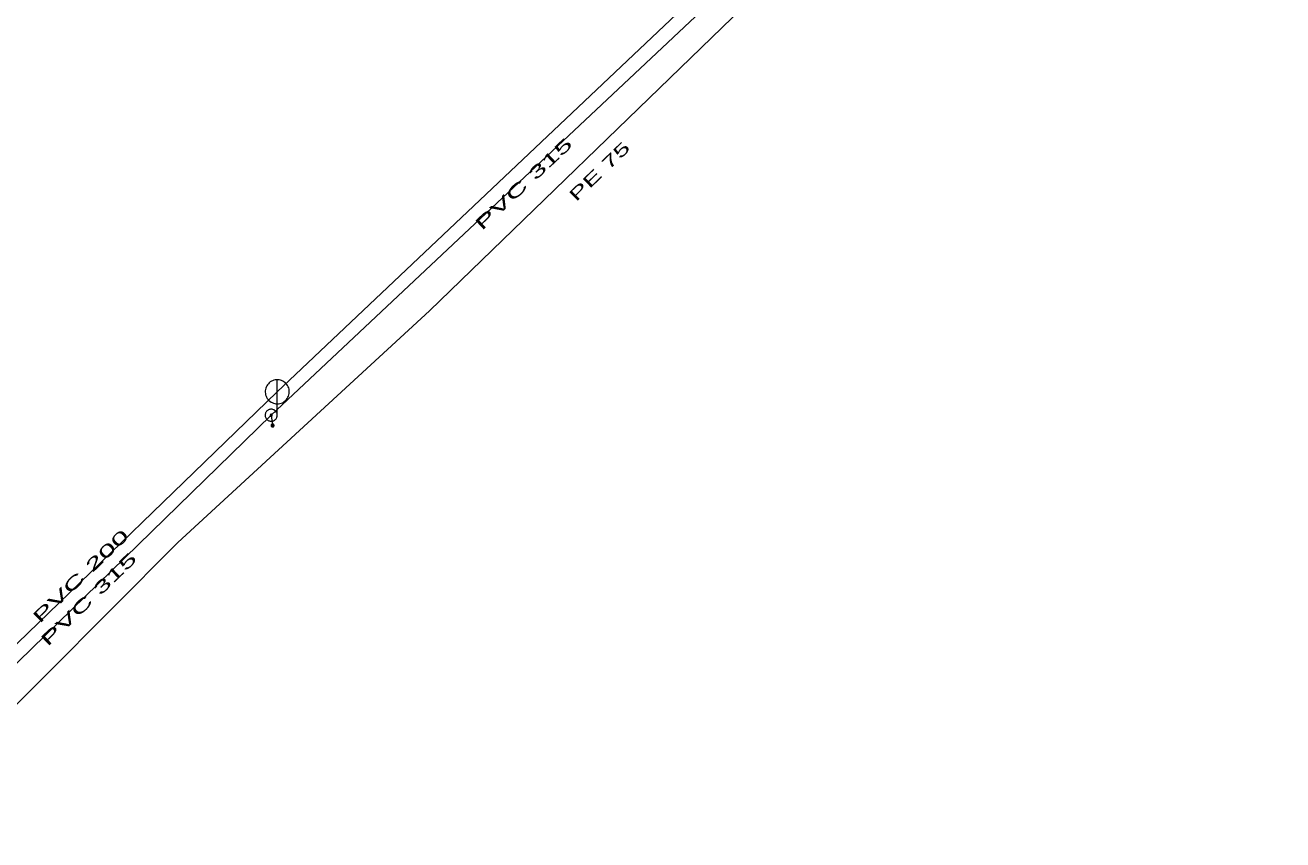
# Model space of a CAD drawing. Extents: x -807203 to -805207, y -993656 to -992505.
# Drawn here: x -806626.5 to -806522, y -992921.3 to -992853.6 of the extents above; entities that cross this region are included whole.
import ezdxf

# ---------------------------------------------------------------- set-up
doc = ezdxf.new("R2010")
doc.units = 0
doc.header["$LTSCALE"] = 0.4
for name, color, linetype, lineweight in [('1', 7, 'Continuous', 13), ('14', 7, 'Continuous', 25), ('17', 7, 'Continuous', 25), ('22', 7, 'Continuous', 13), ('47', 7, 'Continuous', 13), ('9', 7, 'Continuous', 13)]:
    doc.layers.add(name, color=color, linetype=linetype, lineweight=lineweight)

msp = doc.modelspace()

# ---------------------------------------------------------------- linework, layer by layer
at = {"layer": '14'}
for p, q in [((-806569.21, -992849.649), (-806605.559, -992884.039)), ((-806605.559, -992884.039), (-806641.469, -992918.76))]:
    msp.add_line(p, q, dxfattribs=at)
at = {"layer": '14', "lineweight": 13}
msp.add_line((-806606.07, -992885.989), (-806605.949, -992886.839), dxfattribs=at)
at = {"layer": '14'}
msp.add_lwpolyline([(-806661.839, -993034.149), (-806676.42, -993009.03), (-806687.16, -992991.6), (-806684.379, -992974.399), (-806682.55, -992964.73), (-806665.699, -992948.5), (-806650.699, -992933.289), (-806630.39, -992913.17), (-806613.82, -992896.559), (-806592.899, -992877.32), (-806567.719, -992852.94), (-806551.12, -992836.629), (-806563.8, -992821.69), (-806562.329, -992819.699), (-806552.96, -992810.51), (-806551.289, -992809.149), (-806548.55, -992808.109), (-806545.73, -992809.739), (-806532.96, -992817.94), (-806527.999, -992817.239)], dxfattribs=at)
at = {"layer": '17'}
for points in [[(-806606.07, -992885.989), (-806568.51, -992850.699), (-806566.809, -992849.02), (-806561.074, -992843.828), (-806559.778, -992843.379), (-806556.037, -992839.954), (-806552.131, -992836.175), (-806521.969, -992807.139)], [(-806698.289, -992977.488), (-806696.94, -992976.539), (-806688.559, -992968), (-806676.219, -992954.809), (-806667.649, -992946.309), (-806638.16, -992917.219), (-806606.07, -992885.989)]]:
    msp.add_lwpolyline(points, dxfattribs=at)
at = {"layer": '22'}
msp.add_line((-806605.559, -992886.039), (-806605.558, -992883.039), dxfattribs=at)
msp.add_lwpolyline([(-806604.559, -992884.039), (-806604.564, -992883.93), (-806604.582, -992883.822), (-806604.612, -992883.716), (-806604.652, -992883.615), (-806604.704, -992883.518), (-806604.766, -992883.428), (-806604.838, -992883.345), (-806604.918, -992883.271), (-806605.006, -992883.205), (-806605.1, -992883.15), (-806605.2, -992883.105), (-806605.305, -992883.072), (-806605.412, -992883.05), (-806605.521, -992883.04), (-806605.631, -992883.042), (-806605.739, -992883.056), (-806605.846, -992883.081), (-806605.949, -992883.118), (-806606.047, -992883.167), (-806606.139, -992883.225), (-806606.225, -992883.294), (-806606.302, -992883.371), (-806606.371, -992883.457), (-806606.43, -992883.549), (-806606.478, -992883.647), (-806606.515, -992883.75), (-806606.541, -992883.857), (-806606.555, -992883.965), (-806606.558, -992884.075), (-806606.548, -992884.184), (-806606.527, -992884.291), (-806606.493, -992884.395), (-806606.449, -992884.495), (-806606.394, -992884.59), (-806606.328, -992884.678), (-806606.254, -992884.758), (-806606.171, -992884.83), (-806606.081, -992884.892), (-806605.985, -992884.944), (-806605.883, -992884.985), (-806605.778, -992885.015), (-806605.67, -992885.033), (-806605.56, -992885.039), (-806605.451, -992885.033), (-806605.343, -992885.015), (-806605.238, -992884.986), (-806605.136, -992884.945), (-806605.039, -992884.893), (-806604.949, -992884.831), (-806604.866, -992884.76), (-806604.791, -992884.68), (-806604.726, -992884.592), (-806604.67, -992884.498), (-806604.626, -992884.398), (-806604.592, -992884.294), (-806604.57, -992884.186), (-806604.56, -992884.077)], close=True, dxfattribs=at)
at = {"layer": '47'}
for points in [[(-806605.705, -992885.646), (-806605.743, -992885.61), (-806605.784, -992885.578), (-806605.829, -992885.551), (-806605.875, -992885.528), (-806605.925, -992885.51), (-806605.976, -992885.498), (-806606.028, -992885.491), (-806606.08, -992885.489), (-806606.132, -992885.493), (-806606.184, -992885.502), (-806606.234, -992885.516), (-806606.283, -992885.537), (-806606.329, -992885.561), (-806606.372, -992885.591), (-806606.412, -992885.624), (-806606.448, -992885.662), (-806606.48, -992885.703), (-806606.508, -992885.748), (-806606.53, -992885.794), (-806606.548, -992885.844), (-806606.56, -992885.895), (-806606.568, -992885.948), (-806606.569, -992886), (-806606.566, -992886.052), (-806606.556, -992886.103), (-806606.542, -992886.153), (-806606.522, -992886.202), (-806606.497, -992886.248), (-806606.467, -992886.291), (-806606.434, -992886.331), (-806606.396, -992886.367), (-806606.355, -992886.399), (-806606.31, -992886.427), (-806606.264, -992886.449), (-806606.214, -992886.467), (-806606.163, -992886.48), (-806606.111, -992886.487), (-806606.059, -992886.489), (-806606.006, -992886.485), (-806605.955, -992886.475), (-806605.905, -992886.461), (-806605.857, -992886.442), (-806605.81, -992886.416), (-806605.767, -992886.386), (-806605.727, -992886.353), (-806605.691, -992886.315), (-806605.659, -992886.274), (-806605.631, -992886.23), (-806605.609, -992886.183), (-806605.591, -992886.133), (-806605.578, -992886.082), (-806605.571, -992886.031), (-806605.57, -992885.979), (-806605.574, -992885.926), (-806605.583, -992885.874), (-806605.597, -992885.824), (-806605.617, -992885.776), (-806605.642, -992885.729), (-806605.672, -992885.686)], [(-806606.01, -992885.932), (-806606.016, -992885.926), (-806606.023, -992885.921), (-806606.03, -992885.917), (-806606.037, -992885.913), (-806606.046, -992885.91), (-806606.054, -992885.908), (-806606.063, -992885.907), (-806606.071, -992885.906), (-806606.08, -992885.908), (-806606.088, -992885.909), (-806606.097, -992885.911), (-806606.105, -992885.915), (-806606.112, -992885.919), (-806606.119, -992885.923), (-806606.126, -992885.929), (-806606.132, -992885.935), (-806606.137, -992885.942), (-806606.141, -992885.949), (-806606.145, -992885.956), (-806606.148, -992885.965), (-806606.15, -992885.973), (-806606.151, -992885.982), (-806606.152, -992885.99), (-806606.151, -992885.999), (-806606.149, -992886.007), (-806606.147, -992886.016), (-806606.143, -992886.024), (-806606.139, -992886.031), (-806606.135, -992886.038), (-806606.129, -992886.045), (-806606.123, -992886.051), (-806606.116, -992886.056), (-806606.109, -992886.06), (-806606.102, -992886.064), (-806606.093, -992886.067), (-806606.085, -992886.069), (-806606.076, -992886.07), (-806606.068, -992886.071), (-806606.059, -992886.07), (-806606.051, -992886.068), (-806606.042, -992886.066), (-806606.034, -992886.062), (-806606.027, -992886.058), (-806606.02, -992886.054), (-806606.013, -992886.048), (-806606.007, -992886.042), (-806606.002, -992886.035), (-806605.998, -992886.028), (-806605.994, -992886.021), (-806605.991, -992886.012), (-806605.989, -992886.004), (-806605.988, -992885.995), (-806605.987, -992885.987), (-806605.989, -992885.978), (-806605.99, -992885.97), (-806605.992, -992885.961), (-806605.996, -992885.953), (-806606, -992885.946), (-806606.004, -992885.939)]]:
    msp.add_lwpolyline(points, close=True, dxfattribs=at)
at = {"layer": '9'}
for points in [[(-806606.075, -992886.839), (-806606.075, -992886.852), (-806606.073, -992886.865), (-806606.07, -992886.878), (-806606.065, -992886.89), (-806606.059, -992886.902), (-806606.052, -992886.913), (-806606.044, -992886.923), (-806606.034, -992886.933), (-806606.024, -992886.941), (-806606.013, -992886.948), (-806606.001, -992886.954), (-806605.989, -992886.959), (-806605.976, -992886.962), (-806605.963, -992886.964), (-806605.95, -992886.966), (-806605.937, -992886.965), (-806605.924, -992886.963), (-806605.911, -992886.96), (-806605.899, -992886.955), (-806605.887, -992886.949), (-806605.876, -992886.942), (-806605.866, -992886.934), (-806605.856, -992886.924), (-806605.848, -992886.914), (-806605.841, -992886.903), (-806605.835, -992886.891), (-806605.83, -992886.879), (-806605.827, -992886.866), (-806605.825, -992886.853), (-806605.823, -992886.84), (-806605.824, -992886.827), (-806605.826, -992886.814), (-806605.829, -992886.801), (-806605.834, -992886.789), (-806605.84, -992886.777), (-806605.847, -992886.766), (-806605.855, -992886.756), (-806605.865, -992886.746), (-806605.875, -992886.738), (-806605.886, -992886.731), (-806605.898, -992886.725), (-806605.91, -992886.72), (-806605.923, -992886.717), (-806605.936, -992886.715), (-806605.949, -992886.714), (-806605.962, -992886.714), (-806605.975, -992886.716), (-806605.988, -992886.719), (-806606, -992886.724), (-806606.012, -992886.73), (-806606.023, -992886.737), (-806606.033, -992886.745), (-806606.043, -992886.755), (-806606.051, -992886.765), (-806606.058, -992886.776), (-806606.064, -992886.788), (-806606.069, -992886.8), (-806606.072, -992886.813), (-806606.074, -992886.826)], [(-806606.055, -992886.839), (-806606.056, -992886.85), (-806606.054, -992886.861), (-806606.051, -992886.872), (-806606.047, -992886.882), (-806606.042, -992886.892), (-806606.036, -992886.901), (-806606.029, -992886.91), (-806606.021, -992886.918), (-806606.012, -992886.925), (-806606.003, -992886.931), (-806605.993, -992886.936), (-806605.983, -992886.94), (-806605.972, -992886.943), (-806605.961, -992886.946), (-806605.95, -992886.946), (-806605.939, -992886.946), (-806605.928, -992886.944), (-806605.917, -992886.941), (-806605.907, -992886.937), (-806605.897, -992886.932), (-806605.888, -992886.926), (-806605.879, -992886.919), (-806605.871, -992886.911), (-806605.864, -992886.902), (-806605.858, -992886.893), (-806605.853, -992886.883), (-806605.849, -992886.873), (-806605.846, -992886.862), (-806605.844, -992886.851), (-806605.843, -992886.84), (-806605.843, -992886.829), (-806605.845, -992886.818), (-806605.848, -992886.807), (-806605.852, -992886.797), (-806605.857, -992886.787), (-806605.863, -992886.778), (-806605.87, -992886.769), (-806605.878, -992886.761), (-806605.887, -992886.754), (-806605.896, -992886.748), (-806605.906, -992886.743), (-806605.916, -992886.739), (-806605.927, -992886.736), (-806605.938, -992886.734), (-806605.949, -992886.734), (-806605.96, -992886.733), (-806605.971, -992886.735), (-806605.982, -992886.738), (-806605.992, -992886.742), (-806606.002, -992886.747), (-806606.011, -992886.753), (-806606.02, -992886.76), (-806606.028, -992886.768), (-806606.035, -992886.777), (-806606.041, -992886.786), (-806606.046, -992886.796), (-806606.05, -992886.806), (-806606.053, -992886.817), (-806606.055, -992886.828)], [(-806606.036, -992886.839), (-806606.036, -992886.848), (-806606.035, -992886.857), (-806606.032, -992886.866), (-806606.029, -992886.874), (-806606.025, -992886.882), (-806606.02, -992886.89), (-806606.014, -992886.897), (-806606.008, -992886.903), (-806606.001, -992886.909), (-806605.993, -992886.914), (-806605.985, -992886.918), (-806605.977, -992886.921), (-806605.968, -992886.924), (-806605.959, -992886.925), (-806605.95, -992886.927), (-806605.941, -992886.926), (-806605.932, -992886.925), (-806605.923, -992886.922), (-806605.915, -992886.919), (-806605.907, -992886.915), (-806605.899, -992886.91), (-806605.892, -992886.904), (-806605.886, -992886.898), (-806605.88, -992886.891), (-806605.875, -992886.883), (-806605.871, -992886.875), (-806605.868, -992886.867), (-806605.865, -992886.858), (-806605.864, -992886.849), (-806605.862, -992886.84), (-806605.863, -992886.831), (-806605.864, -992886.822), (-806605.867, -992886.813), (-806605.87, -992886.805), (-806605.874, -992886.797), (-806605.879, -992886.789), (-806605.885, -992886.782), (-806605.891, -992886.776), (-806605.898, -992886.77), (-806605.906, -992886.765), (-806605.914, -992886.761), (-806605.922, -992886.758), (-806605.931, -992886.755), (-806605.94, -992886.754), (-806605.949, -992886.753), (-806605.958, -992886.753), (-806605.967, -992886.754), (-806605.976, -992886.757), (-806605.984, -992886.76), (-806605.992, -992886.764), (-806606, -992886.769), (-806606.007, -992886.775), (-806606.013, -992886.781), (-806606.019, -992886.788), (-806606.024, -992886.796), (-806606.028, -992886.804), (-806606.031, -992886.812), (-806606.034, -992886.821), (-806606.035, -992886.83)], [(-806606.016, -992886.839), (-806606.016, -992886.846), (-806606.015, -992886.853), (-806606.014, -992886.86), (-806606.011, -992886.866), (-806606.008, -992886.872), (-806606.004, -992886.878), (-806606, -992886.884), (-806605.995, -992886.889), (-806605.989, -992886.893), (-806605.983, -992886.897), (-806605.977, -992886.9), (-806605.971, -992886.903), (-806605.964, -992886.904), (-806605.957, -992886.907), (-806605.95, -992886.907), (-806605.943, -992886.907), (-806605.936, -992886.905), (-806605.929, -992886.904), (-806605.923, -992886.901), (-806605.916, -992886.898), (-806605.911, -992886.894), (-806605.905, -992886.89), (-806605.9, -992886.885), (-806605.896, -992886.879), (-806605.892, -992886.873), (-806605.889, -992886.867), (-806605.886, -992886.861), (-806605.884, -992886.854), (-806605.883, -992886.847), (-806605.882, -992886.84), (-806605.882, -992886.833), (-806605.883, -992886.826), (-806605.885, -992886.819), (-806605.888, -992886.813), (-806605.891, -992886.806), (-806605.895, -992886.801), (-806605.899, -992886.795), (-806605.904, -992886.79), (-806605.91, -992886.786), (-806605.915, -992886.782), (-806605.922, -992886.779), (-806605.928, -992886.776), (-806605.935, -992886.774), (-806605.942, -992886.773), (-806605.949, -992886.773), (-806605.956, -992886.773), (-806605.963, -992886.773), (-806605.97, -992886.775), (-806605.976, -992886.778), (-806605.982, -992886.781), (-806605.988, -992886.785), (-806605.994, -992886.789), (-806605.999, -992886.794), (-806606.003, -992886.8), (-806606.007, -992886.805), (-806606.01, -992886.812), (-806606.013, -992886.818), (-806606.014, -992886.825), (-806606.016, -992886.832)], [(-806605.996, -992886.839), (-806605.996, -992886.844), (-806605.996, -992886.849), (-806605.995, -992886.854), (-806605.993, -992886.858), (-806605.991, -992886.863), (-806605.988, -992886.867), (-806605.985, -992886.87), (-806605.981, -992886.874), (-806605.978, -992886.877), (-806605.974, -992886.88), (-806605.969, -992886.882), (-806605.965, -992886.884), (-806605.96, -992886.885), (-806605.955, -992886.887), (-806605.95, -992886.887), (-806605.945, -992886.887), (-806605.94, -992886.886), (-806605.935, -992886.885), (-806605.931, -992886.883), (-806605.926, -992886.881), (-806605.922, -992886.878), (-806605.918, -992886.875), (-806605.915, -992886.871), (-806605.912, -992886.868), (-806605.909, -992886.864), (-806605.907, -992886.859), (-806605.905, -992886.855), (-806605.904, -992886.85), (-806605.903, -992886.845), (-806605.902, -992886.84), (-806605.902, -992886.835), (-806605.903, -992886.83), (-806605.904, -992886.825), (-806605.906, -992886.821), (-806605.908, -992886.816), (-806605.911, -992886.812), (-806605.914, -992886.808), (-806605.917, -992886.805), (-806605.921, -992886.802), (-806605.925, -992886.799), (-806605.93, -992886.797), (-806605.934, -992886.795), (-806605.939, -992886.794), (-806605.944, -992886.793), (-806605.949, -992886.793), (-806605.954, -992886.793), (-806605.959, -992886.794), (-806605.964, -992886.794), (-806605.968, -992886.796), (-806605.973, -992886.798), (-806605.977, -992886.801), (-806605.98, -992886.804), (-806605.984, -992886.807), (-806605.987, -992886.811), (-806605.99, -992886.815), (-806605.992, -992886.82), (-806605.994, -992886.824), (-806605.995, -992886.829), (-806605.996, -992886.834)], [(-806605.976, -992886.839), (-806605.976, -992886.842), (-806605.977, -992886.845), (-806605.976, -992886.847), (-806605.975, -992886.85), (-806605.974, -992886.853), (-806605.972, -992886.855), (-806605.97, -992886.857), (-806605.968, -992886.859), (-806605.966, -992886.861), (-806605.964, -992886.863), (-806605.961, -992886.865), (-806605.958, -992886.866), (-806605.956, -992886.866), (-806605.953, -992886.867), (-806605.95, -992886.867), (-806605.947, -992886.867), (-806605.944, -992886.867), (-806605.941, -992886.866), (-806605.939, -992886.865), (-806605.936, -992886.864), (-806605.934, -992886.862), (-806605.931, -992886.86), (-806605.929, -992886.858), (-806605.928, -992886.856), (-806605.926, -992886.854), (-806605.925, -992886.851), (-806605.923, -992886.848), (-806605.923, -992886.846), (-806605.922, -992886.843), (-806605.921, -992886.84), (-806605.922, -992886.837), (-806605.922, -992886.834), (-806605.923, -992886.831), (-806605.924, -992886.829), (-806605.925, -992886.826), (-806605.927, -992886.824), (-806605.928, -992886.821), (-806605.93, -992886.819), (-806605.933, -992886.818), (-806605.935, -992886.816), (-806605.938, -992886.815), (-806605.94, -992886.814), (-806605.943, -992886.813), (-806605.946, -992886.813), (-806605.949, -992886.812), (-806605.952, -992886.813), (-806605.955, -992886.812), (-806605.957, -992886.814), (-806605.96, -992886.814), (-806605.963, -992886.815), (-806605.965, -992886.817), (-806605.967, -992886.818), (-806605.969, -992886.82), (-806605.971, -992886.823), (-806605.973, -992886.825), (-806605.974, -992886.828), (-806605.975, -992886.83), (-806605.976, -992886.833), (-806605.976, -992886.836)], [(-806605.957, -992886.839), (-806605.957, -992886.841), (-806605.957, -992886.841), (-806605.956, -992886.841), (-806605.956, -992886.843), (-806605.957, -992886.844), (-806605.955, -992886.844), (-806605.955, -992886.844), (-806605.955, -992886.846), (-806605.955, -992886.846), (-806605.954, -992886.847), (-806605.952, -992886.847), (-806605.952, -992886.847), (-806605.952, -992886.848), (-806605.95, -992886.848), (-806605.95, -992886.848), (-806605.949, -992886.848), (-806605.948, -992886.848), (-806605.948, -992886.847), (-806605.947, -992886.847), (-806605.945, -992886.847), (-806605.945, -992886.846), (-806605.945, -992886.846), (-806605.944, -992886.845), (-806605.944, -992886.845), (-806605.942, -992886.844), (-806605.942, -992886.843), (-806605.941, -992886.842), (-806605.941, -992886.842), (-806605.941, -992886.841), (-806605.941, -992886.84), (-806605.941, -992886.839), (-806605.941, -992886.838), (-806605.941, -992886.838), (-806605.942, -992886.837), (-806605.942, -992886.836), (-806605.943, -992886.835), (-806605.943, -992886.835), (-806605.944, -992886.834), (-806605.944, -992886.834), (-806605.945, -992886.833), (-806605.946, -992886.833), (-806605.947, -992886.832), (-806605.947, -992886.832), (-806605.948, -992886.832), (-806605.949, -992886.832), (-806605.95, -992886.832), (-806605.951, -992886.832), (-806605.951, -992886.832), (-806605.952, -992886.833), (-806605.953, -992886.832), (-806605.954, -992886.834), (-806605.954, -992886.834), (-806605.955, -992886.834), (-806605.955, -992886.834), (-806605.956, -992886.836), (-806605.956, -992886.837), (-806605.956, -992886.838), (-806605.957, -992886.838), (-806605.957, -992886.839)]]:
    msp.add_lwpolyline(points, close=True, dxfattribs=at)

# ---------------------------------------------------------------- texts
at = {"layer": '1'}
for s, rotation, width, p in [('PVC 315 ', 43, 1.95, (-806588.562, -992870.691)), ('PE 75 ', 44, 1.75, (-806580.724, -992868.295)), ('PVC 200 ', 44, 1.95, (-806625.309, -992903.339)), ('PVC 315 ', 44, 1.95, (-806624.65, -992905.259))]:
    msp.add_text(s, height=1, rotation=rotation, dxfattribs=dict(at, width=width)).set_placement(p)

doc.saveas('drawing.dxf')
